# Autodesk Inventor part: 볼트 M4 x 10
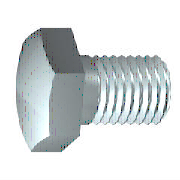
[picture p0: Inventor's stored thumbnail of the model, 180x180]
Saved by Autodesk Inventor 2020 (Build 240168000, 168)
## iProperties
Created: 2012-02
Part Number: 볼트 M4 x 10
Material: 스테인리스강
Description: 6각 머리 나사
Document SubType Name: Modeling
Standard: ISO 4017
Designer: mduedu
Standard Revision: Third edition 1999-08-15
Standards Organization: ISO
Language: ko-KR
Size Designation: M4 x 10
Categories: <MemberInstance><Categories><Category DisplayName="조임쇠" InternalName="e4da775c-781d-43d5-af7c-5136215cf5a6" Mnemonic="FSTN"><Category DisplayName="볼트" InternalN
Density: 8.08 g/cm^3
Appearance: 기본값
IsCustomPart: 0
Author: mduedu
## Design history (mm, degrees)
sketch "스케치1"
  geometry: L1 (0, 3.015)-(0, 2); L2 (1.25, 2)-(10, 2); L3 (10, 2)-(10, 0); L4 (10, 0)-(-0.4, 0); L5 (-2.48, 0)-(12.08, 0) reference; L6 (-0.4, 0)-(-0.4, 3.015); L7 (-0.4, 3.015)-(0, 3.015); L8 (1.25, 2)-(0.82, 2); L9 (0.82, 2)-(0, 2); L10 (0, -0.603)-(0, 3.618) reference
  constraints: 16 end point, 2 collinear, 2 perpendicular, 1 parallel
  dimensions: "d0" = 10 distance between parallel lines of L3 L1 (= NLG); "d1" = 8.75 distance from line of L2.start L3 (= GEL); "d2" = 4 diameter of L2 L4 (= GD); "d9" = 0.4001 distance between parallel lines of L6 L1 (computed from SD); "d10" = 6.03 diameter of L7 L4 (= SD2); "d13" = 0.42952 distance of L2.start L8.end (computed from GAL); "d14" = 4 diameter of L9 L4 (= BDM)
revolve "본체" sketch "스케치1" stored, may be unused: angle "d12" = 90 deg
sketch "스케치2"
  geometry: L1 (0, 4.041)-(3.5, 2.021); L2 (3.5, 2.021)-(3.5, -2.021); L3 (3.5, -2.021)-(0, -4.041); L4 (0, -4.041)-(-3.5, -2.021); L5 (-3.5, -2.021)-(-3.5, 2.021); L6 (-3.5, 2.021)-(0, 4.041); 2 further points
  constraints: 12 end point, 1 coincident, 1 vertical, 11 other
  dimensions: "d11" = 7 distance between parallel lines of L5 L2 (= SW)
extrude "머리" join sketch "스케치2" distance "d3" = 2.4 (= KOH - SD); taper "d4" = 0 deg
sketch "스케치4"
  geometry: L1 (-2.8, 3.5)-(-2.8, 4.041); L2 (-2.8, 4.041)-(-2.487, 4.041); L3 (-2.487, 4.041)-(-2.8, 3.5); L4 (-3.28, 0)-(0.08, 0) reference; L5 (-0.4, 4.041)-(-2.8, 4.041) reference; L6 (-2.8, 2.021)-(-2.8, 4.041) reference
  constraints: 6 end point, 2 collinear, 1 perpendicular, 1 vertical
  dimensions: "d5" = 30 deg angle of L3 L1 (= ANG1); "d19" = 7 diameter of L1.start L4 (= SW0)
revolve "모따기1" sketch "스케치4" stored, may be unused: angle "d21" = 90 deg
workplane "Work Plane1"
body "Solid1"
feature "스레드" dims "d15" = 8.75 (= GEL), "d16" = 0
chamfer "모따기2" distance "d6" = 0.42941 (= -0.5 x SPD + 0.5 x GD); stored, may be unused: second distance "d7" = 0.42952 (computed from GUL), angle "d55" = 45 deg
other parameters: "NLG" = 10 [user parameter; used in 1 equation term], "GD" = 4 (= NND) [user parameter; used in 2 equation terms], "BDM" = 4 (= NND) [user parameter; used in 1 equation term], "KOH" = 2.8 [user parameter; used in 1 equation term], "GEL" = 8.75 [user parameter; used in 2 equation terms], "SW" = 7 [user parameter; used in 2 equation terms], "SW0" = 7 (= SW) [user parameter; used in 1 equation term], "SPD" = 3.14117 (= NND - 1.2269 x PTC) [user parameter; used in 1 equation term], "SD2" = 6.03 [user parameter; used in 2 equation terms], "SD" = 0.4 [user parameter; used in 2 equation terms], "ANG1" = 30 deg [user parameter; used in 1 equation term], "GAL" = 0.42941 (= 0.61345 x PTC) [user parameter; used in 1 equation term], "GUL" = 0.42941 (= 0.61345 x PTC) [user parameter; used in 1 equation term], "d8" = 0, "RR" = 0.2 [user parameter], "d57" = 0, "d58" = 0, "TPU" = 14.28571 (computed from PTC) [user parameter], "GD1" = 3.14117 (= THREADDIA - 1.2269 x PTC) [user parameter], "THREADDIA" = 4 [user parameter; used in 1 equation term], "SDH" = 6.03 (= SD2) [user parameter], "SDHG" = 2.1 [user parameter], "TOA" = 30 deg [user parameter], "PTC" = 0.7 [user parameter; used in 5 equation terms], "NND" = 4 [user parameter; used in 3 equation terms], "E0" = 8.085 [user parameter]
